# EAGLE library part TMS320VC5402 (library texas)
Fixed-Point Digital Signal Processor Source: tms320vc5402.pdf
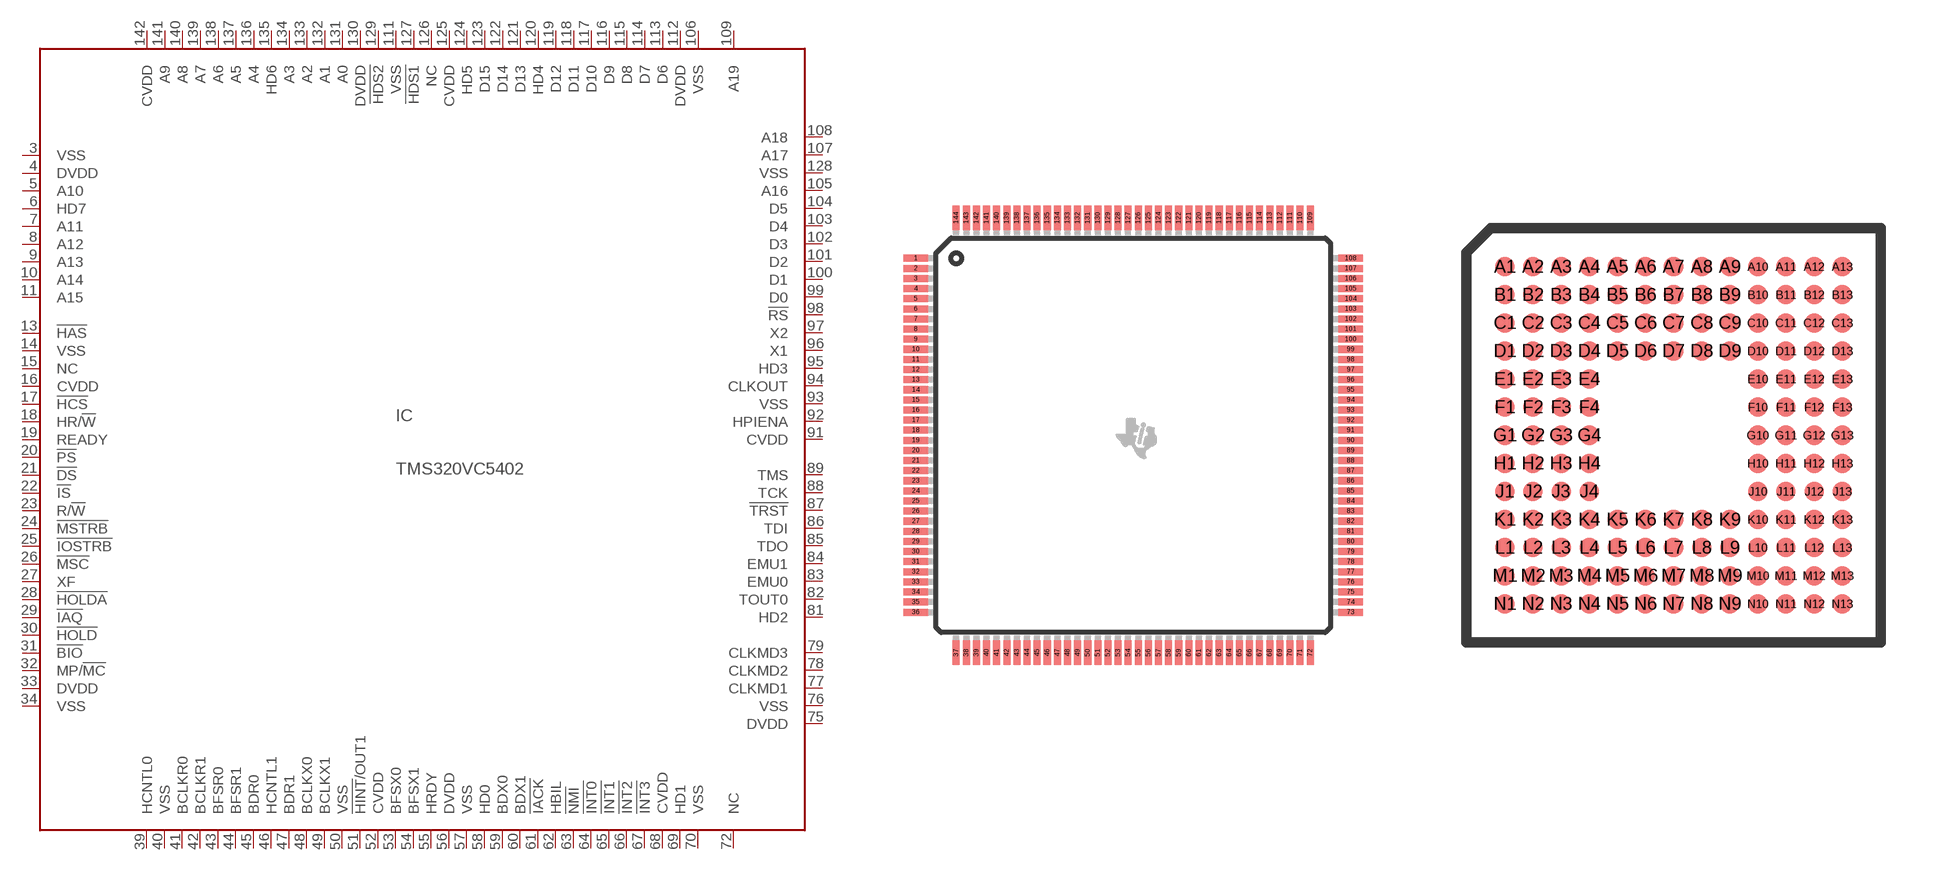
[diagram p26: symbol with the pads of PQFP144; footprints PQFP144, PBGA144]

Designator prefix IC

## TMS320VC5402PGE (MF: TEXAS INSTRUMENTS; MPN: TMS320VC5402PGE100; OC_FARNELL: 1214352; OC_NEWARK: 72K9586)  [PQFP144]
1  NC  nc
2  NC  nc
3  VSS  pwr
4  DVDD  pwr
5  A10  hiz
6  HD7  hiz
7  A11  hiz
8  A12  hiz
9  A13  hiz
10  A14  hiz
11  A15  hiz
12  NC  nc
13  !HAS  in
14  VSS  pwr
15  NC  nc
16  CVDD  pwr
17  !HCS  in
18  HR/!W  in
19  READY  in
20  !PS  hiz
21  !DS  hiz
22  !IS  hiz
23  R/!W  hiz
24  !MSTRB  hiz
25  !IOSTRB  hiz
26  !MSC  hiz
27  XF  hiz
28  !HOLDA  hiz
29  !IAQ  hiz
30  !HOLD  in
31  !BIO  in
32  MP/!MC  in
33  DVDD  pwr
34  VSS  pwr
35  NC  nc
36  NC  nc
37  NC  nc
38  NC  nc
39  HCNTL0  in
40  VSS  pwr
41  BCLKR0  hiz
42  BCLKR1  hiz
43  BFSR0  hiz
44  BFSR1  hiz
45  BDR0  in
46  HCNTL1  in
47  BDR1  in
48  BCLKX0  hiz
49  BCLKX1  hiz
50  VSS  pwr
51  !HINT!/OUT1  hiz
52  CVDD  pwr
53  BFSX0  hiz
54  BFSX1  hiz
55  HRDY  hiz
56  DVDD  pwr
57  VSS  pwr
58  HD0  hiz
59  BDX0  hiz
60  BDX1  hiz
61  !IACK  hiz
62  HBIL  in
63  !NMI  in
64  !INT0  in
65  !INT1  in
66  !INT2  in
67  !INT3  in
68  CVDD  pwr
69  HD1  hiz
70  VSS  pwr
71  NC  nc
72  NC  nc
73  NC  nc
74  NC  nc
75  DVDD  pwr
76  VSS  pwr
77  CLKMD1  in
78  CLKMD2  in
79  CLKMD3  in
80  NC  nc
81  HD2  hiz
82  TOUT0  hiz
83  EMU0  hiz
84  EMU1  hiz
85  TDO  hiz
86  TDI  in
87  !TRST  in
88  TCK  in
89  TMS  in
90  NC  nc
91  CVDD  pwr
92  HPIENA  in
93  VSS  nc
94  CLKOUT  hiz
95  HD3  hiz
96  X1  out
97  X2  in
98  !RS  in
99  D0  hiz
100  D1  hiz
101  D2  hiz
102  D3  hiz
103  D4  hiz
104  D5  hiz
105  A16  hiz
106  VSS  pwr
107  A17  hiz
108  A18  hiz
109  A19  hiz
110  NC  nc
111  VSS  pwr
112  DVDD  pwr
113  D6  hiz
114  D7  hiz
115  D8  hiz
116  D9  hiz
117  D10  hiz
118  D11  hiz
119  D12  hiz
120  HD4  hiz
121  D13  hiz
122  D14  hiz
123  D15  hiz
124  HD5  hiz
125  CVDD  pwr
126  NC  nc
127  !HDS1  in
128  VSS  pwr
129  !HDS2  in
130  DVDD  pwr
131  A0  hiz
132  A1  hiz
133  A2  hiz
134  A3  hiz
135  HD6  hiz
136  A4  hiz
137  A5  hiz
138  A6  hiz
139  A7  hiz
140  A8  hiz
141  A9  hiz
142  CVDD  pwr
143  NC  nc
144  NC  nc

## TMS320VC5402GGU (MF: TEXAS INSTRUMENTS; MPN: TMS320VC5402GGU100; OC_FARNELL: 1690105; OC_NEWARK: 76C9605)  [PBGA144]
A1  NC  nc
A2  NC  nc
A3  A8  hiz
A4  A5  hiz
A5  A2  hiz
A6  !HDS2  in
A7  NC  nc
A8  HD5  hiz
A9  HD4  hiz
A10  D9  hiz
A11  DVDD  pwr
A12  NC  nc
A13  A19  hiz
B1  NC  nc
B2  NC  nc
B3  A9  hiz
B4  A6  hiz
B5  A3  hiz
B6  DVDD  pwr
B7  CVDD  pwr
B8  D15  hiz
B9  D12  hiz
B10  D8  hiz
B11  VSS  pwr
B12  A18  hiz
B13  A17  hiz
C1  DVDD  pwr
C2  VSS  pwr
C3  CVDD  pwr
C4  A7  hiz
C5  HD6  hiz
C6  A0  hiz
C7  !HDS1  in
C8  D14  hiz
C9  D11  hiz
C10  D7  hiz
C11  VSS  pwr
C12  A16  hiz
C13  D5  hiz
D1  A12  hiz
D2  A11  hiz
D3  HD7  hiz
D4  A10  hiz
D5  A4  hiz
D6  A1  hiz
D7  VSS  pwr
D8  D13  hiz
D9  D10  hiz
D10  D6  hiz
D11  D4  hiz
D12  D3  hiz
D13  D2  hiz
E1  NC  nc
E2  A15  hiz
E3  A14  hiz
E4  A13  hiz
E10  D1  hiz
E11  D0  hiz
E12  !RS  in
E13  X2  in
F1  CVDD  pwr
F2  NC  nc
F3  VSS  pwr
F4  !HAS  in
F10  X1  out
F11  HD3  hiz
F12  CLKOUT  hiz
F13  VSS  pwr
G1  HR/!W  in
G2  !HCS  in
G3  READY  in
G4  !PS  hiz
G10  HPIENA  in
G11  CVDD  pwr
G12  TMS  in
G13  NC  nc
H1  !DS  hiz
H2  !IS  hiz
H3  R/!W  hiz
H4  !MSTRB  hiz
H10  TDO  hiz
H11  TDI  in
H12  !TRST  in
H13  TCK  in
J1  !IOSTRB  hiz
J2  !MSC  hiz
J3  XF  hiz
J4  !HOLDA  hiz
J10  HD2  hiz
J11  TOUT0  hiz
J12  EMU0  hiz
J13  EMU1  hiz
K1  !IAQ  hiz
K2  !HOLD  in
K3  !BIO  in
K4  BCLKR0  hiz
K5  BDR0  in
K6  BCLKX1  hiz
K7  DVDD  pwr
K8  BDX1  hiz
K9  !INT0  in
K10  CLKMD1  in
K11  CLKMD2  in
K12  CLKMD3  in
K13  NC  nc
L1  MP/!MC  in
L2  DVDD  pwr
L3  VSS  pwr
L4  BCLKR1  hiz
L5  HCNTL1  in
L6  VSS  nc
L7  HRDY  hiz
L8  BDX0  hiz
L9  !NMI  in
L10  !INT3  in
L11  VSS  pwr
L12  DVDD  pwr
L13  VSS  pwr
M1  NC  nc
M2  NC  nc
M3  HCNTL0  in
M4  BFSR0  hiz
M5  BDR1  in
M6  !HINT!/OUT1  hiz
M7  BFSX0  hiz
M8  HD0  hiz
M9  HBIL  in
M10  !INT2  in
M11  HD1  hiz
M12  NC  nc
M13  NC  nc
N1  NC  nc
N2  NC  nc
N3  VSS  pwr
N4  BFSR1  hiz
N5  BCLKX0  hiz
N6  CVDD  pwr
N7  BFSX1  hiz
N8  VSS  pwr
N9  !IACK  hiz
N10  !INT1  in
N11  CVDD  pwr
N12  NC  nc
N13  NC  nc

## Footprint PQFP144 (pad centres in mm)
Platic Quad Flat Package PGE (S-PQFP-G144)
smd 1.2 x 0.35: 1 -10.75,8.75; 2 -10.75,8.25; 3 -10.75,7.75; 4 -10.75,7.25; 5 -10.75,6.75; 6 -10.75,6.25; 7 -10.75,5.75; 8 -10.75,5.25; 9 -10.75,4.75; 10 -10.75,4.25; 11 -10.75,3.75; 12 -10.75,3.25; 13 -10.75,2.75; 14 -10.75,2.25; 15 -10.75,1.75; 16 -10.75,1.25; 17 -10.75,0.75; 18 -10.75,0.25; 19 -10.75,-0.25; 20 -10.75,-0.75; 21 -10.75,-1.25; 22 -10.75,-1.75; 23 -10.75,-2.25; 24 -10.75,-2.75; 25 -10.75,-3.25; 26 -10.75,-3.75; 27 -10.75,-4.25; 28 -10.75,-4.75; 29 -10.75,-5.25; 30 -10.75,-5.75; 31 -10.75,-6.25; 32 -10.75,-6.75; 33 -10.75,-7.25; 34 -10.75,-7.75; 35 -10.75,-8.25; 36 -10.75,-8.75; 73 10.75,-8.75; 74 10.75,-8.25; 75 10.75,-7.75; 76 10.75,-7.25; 77 10.75,-6.75; 78 10.75,-6.25; 79 10.75,-5.75; 80 10.75,-5.25; 81 10.75,-4.75; 82 10.75,-4.25; 83 10.75,-3.75; 84 10.75,-3.25; 85 10.75,-2.75; 86 10.75,-2.25; 87 10.75,-1.75; 88 10.75,-1.25; 89 10.75,-0.75; 90 10.75,-0.25; 91 10.75,0.25; 92 10.75,0.75; 93 10.75,1.25; 94 10.75,1.75; 95 10.75,2.25; 96 10.75,2.75; 97 10.75,3.25; 98 10.75,3.75; 99 10.75,4.25; 100 10.75,4.75; 101 10.75,5.25; 102 10.75,5.75; 103 10.75,6.25; 104 10.75,6.75; 105 10.75,7.25; 106 10.75,7.75; 107 10.75,8.25; 108 10.75,8.75
smd 0.35 x 1.2: 37 -8.75,-10.75; 38 -8.25,-10.75; 39 -7.75,-10.75; 40 -7.25,-10.75; 41 -6.75,-10.75; 42 -6.25,-10.75; 43 -5.75,-10.75; 44 -5.25,-10.75; 45 -4.75,-10.75; 46 -4.25,-10.75; 47 -3.75,-10.75; 48 -3.25,-10.75; 49 -2.75,-10.75; 50 -2.25,-10.75; 51 -1.75,-10.75; 52 -1.25,-10.75; 53 -0.75,-10.75; 54 -0.25,-10.75; 55 0.25,-10.75; 56 0.75,-10.75; 57 1.25,-10.75; 58 1.75,-10.75; 59 2.25,-10.75; 60 2.75,-10.75; 61 3.25,-10.75; 62 3.75,-10.75; 63 4.25,-10.75; 64 4.75,-10.75; 65 5.25,-10.75; 66 5.75,-10.75; 67 6.25,-10.75; 68 6.75,-10.75; 69 7.25,-10.75; 70 7.75,-10.75; 71 8.25,-10.75; 72 8.75,-10.75; 109 8.75,10.75; 110 8.25,10.75; 111 7.75,10.75; 112 7.25,10.75; 113 6.75,10.75; 114 6.25,10.75; 115 5.75,10.75; 116 5.25,10.75; 117 4.75,10.75; 118 4.25,10.75; 119 3.75,10.75; 120 3.25,10.75; 121 2.75,10.75; 122 2.25,10.75; 123 1.75,10.75; 124 1.25,10.75; 125 0.75,10.75; 126 0.25,10.75; 127 -0.25,10.75; 128 -0.75,10.75; 129 -1.25,10.75; 130 -1.75,10.75; 131 -2.25,10.75; 132 -2.75,10.75; 133 -3.25,10.75; 134 -3.75,10.75; 135 -4.25,10.75; 136 -4.75,10.75; 137 -5.25,10.75; 138 -5.75,10.75; 139 -6.25,10.75; 140 -6.75,10.75; 141 -7.25,10.75; 142 -7.75,10.75; 143 -8.25,10.75; 144 -8.75,10.75

## Footprint PBGA144 (pad centres in mm)
PLASTIC BALL GRID ARRAY PACKAGE GGU (S-PBGA-N144) Source: tms320vc5402.pdf
smd 0.55 x 0.55: A1 -4.8,4.8; A2 -4,4.8; A3 -3.2,4.8; A4 -2.4,4.8; A5 -1.6,4.8; A6 -0.8,4.8; A7 0,4.8; A8 0.8,4.8; A9 1.6,4.8; A10 2.4,4.8; A11 3.2,4.8; A12 4,4.8; A13 4.8,4.8; B1 -4.8,4; B2 -4,4; B3 -3.2,4; B4 -2.4,4; B5 -1.6,4; B6 -0.8,4; B7 0,4; B8 0.8,4; B9 1.6,4; B10 2.4,4; B11 3.2,4; B12 4,4; B13 4.8,4; C1 -4.8,3.2; C2 -4,3.2; C3 -3.2,3.2; C4 -2.4,3.2; C5 -1.6,3.2; C6 -0.8,3.2; C7 0,3.2; C8 0.8,3.2; C9 1.6,3.2; C10 2.4,3.2; C11 3.2,3.2; C12 4,3.2; C13 4.8,3.2; D1 -4.8,2.4; D2 -4,2.4; D3 -3.2,2.4; D4 -2.4,2.4; D5 -1.6,2.4; D6 -0.8,2.4; D7 0,2.4; D8 0.8,2.4; D9 1.6,2.4; D10 2.4,2.4; D11 3.2,2.4; D12 4,2.4; D13 4.8,2.4; E1 -4.8,1.6; E2 -4,1.6; E3 -3.2,1.6; E4 -2.4,1.6; E10 2.4,1.6; E11 3.2,1.6; E12 4,1.6; E13 4.8,1.6; F1 -4.8,0.8; F2 -4,0.8; F3 -3.2,0.8; F4 -2.4,0.8; F10 2.4,0.8; F11 3.2,0.8; F12 4,0.8; F13 4.8,0.8; G1 -4.8,0; G2 -4,0; G3 -3.2,0; G4 -2.4,0; G10 2.4,0; G11 3.2,0; G12 4,0; G13 4.8,0; H1 -4.8,-0.8; H2 -4,-0.8; H3 -3.2,-0.8; H4 -2.4,-0.8; H10 2.4,-0.8; H11 3.2,-0.8; H12 4,-0.8; H13 4.8,-0.8; J1 -4.8,-1.6; J2 -4,-1.6; J3 -3.2,-1.6; J4 -2.4,-1.6; J10 2.4,-1.6; J11 3.2,-1.6; J12 4,-1.6; J13 4.8,-1.6; K1 -4.8,-2.4; K2 -4,-2.4; K3 -3.2,-2.4; K4 -2.4,-2.4; K5 -1.6,-2.4; K6 -0.8,-2.4; K7 0,-2.4; K8 0.8,-2.4; K9 1.6,-2.4; K10 2.4,-2.4; K11 3.2,-2.4; K12 4,-2.4; K13 4.8,-2.4; L1 -4.8,-3.2; L2 -4,-3.2; L3 -3.2,-3.2; L4 -2.4,-3.2; L5 -1.6,-3.2; L6 -0.8,-3.2; L7 0,-3.2; L8 0.8,-3.2; L9 1.6,-3.2; L10 2.4,-3.2; L11 3.2,-3.2; L12 4,-3.2; L13 4.8,-3.2; M1 -4.8,-4; M2 -4,-4; M3 -3.2,-4; M4 -2.4,-4; M5 -1.6,-4; M6 -0.8,-4; M7 0,-4; M8 0.8,-4; M9 1.6,-4; M10 2.4,-4; M11 3.2,-4; M12 4,-4; M13 4.8,-4; N1 -4.8,-4.8; N2 -4,-4.8; N3 -3.2,-4.8; N4 -2.4,-4.8; N5 -1.6,-4.8; N6 -0.8,-4.8; N7 0,-4.8; N8 0.8,-4.8; N9 1.6,-4.8; N10 2.4,-4.8; N11 3.2,-4.8; N12 4,-4.8; N13 4.8,-4.8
